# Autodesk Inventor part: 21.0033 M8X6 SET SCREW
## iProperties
Created: 2012-10
Part Number: 21.0033 M8X6 SET SCREW
Document SubType Name: Modeling
Designer: Administrator
Density: 7.85 g/cm^3
Material: Steel
Mass: 1.89077 g
Surface Area: 3.03432 cm^2
Volume: 0.240862 cm^3
Author: Administrator
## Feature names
1. Base1
2. Extrusion1
3. Extrusion2
